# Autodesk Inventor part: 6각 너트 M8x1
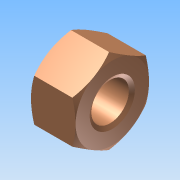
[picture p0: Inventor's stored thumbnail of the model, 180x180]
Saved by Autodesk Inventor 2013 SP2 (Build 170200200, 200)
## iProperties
Created: 2025-10
Part Number: 6각 너트 M8x1
Material: Generic
Document SubType Name: Modeling
Designer: 601
Density: 1 g/cm^3
Author: 601
변환 표준: STEP AP214IS
전처리기: Build: 200, Release: 2013 SP2 Update 6 - Date: Thu 07/17/2014
전송 단위: 밀리미터
불확실성: 0.01
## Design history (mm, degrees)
node "6각 너트 M8x11"
body "Solid1"
node "기준1"
